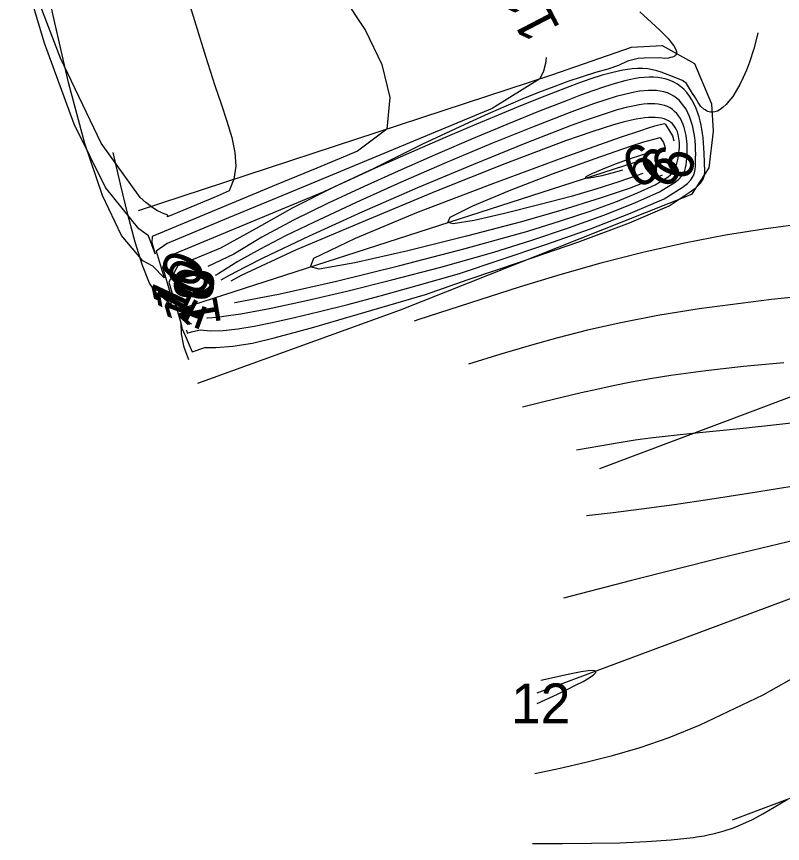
# Model space of a CAD drawing. Extents: x 2602990 to 2605851, y 618069 to 619180.
# Drawn here: x 2603067.49 to 2603105.92, y 618321.38 to 618362.9 of the extents above; entities that cross this region are included whole.
import ezdxf

# ---------------------------------------------------------------- set-up
doc = ezdxf.new("R2010")
doc.units = 0
for name, color, linetype in [('DTM Contours Major', 7, 'Continuous'), ('DTM Contours Major Text', 7, 'Continuous'), ('DTM Contours Minor', 7, 'Continuous'), ('DTM Contours Minor Text', 7, 'Continuous'), ('PH Exist DTM Breakline', 7, 'Continuous')]:
    doc.layers.add(name, color=color, linetype=linetype)

msp = doc.modelspace()

# ---------------------------------------------------------------- linework, layer by layer
at = {"layer": 'DTM Contours Major'}
for points in [[(2603100.888, 618354.321), (2603101.149, 618354.52), (2603101.329, 618354.703), (2603101.443, 618354.877), (2603101.507, 618355.045), (2603101.538, 618355.214), (2603101.551, 618355.387), (2603101.565, 618355.785), (2603101.567, 618355.996), (2603101.563, 618356.211), (2603101.553, 618356.431), (2603101.536, 618356.651), (2603101.517, 618356.829), (2603101.492, 618357.006), (2603101.461, 618357.18), (2603101.424, 618357.352), (2603101.38, 618357.521), (2603101.33, 618357.685), (2603101.259, 618357.879), (2603101.177, 618358.063), (2603101.084, 618358.238), (2603100.98, 618358.402), (2603100.863, 618358.553), (2603100.734, 618358.69), (2603100.605, 618358.802), (2603100.464, 618358.902), (2603100.312, 618358.987), (2603100.148, 618359.059), (2603099.971, 618359.115), (2603099.782, 618359.156), (2603099.598, 618359.18), (2603099.403, 618359.191), (2603099.195, 618359.189), (2603098.975, 618359.173), (2603098.74, 618359.144), (2603098.491, 618359.102), (2603098.057, 618359.007), (2603097.581, 618358.879), (2603097.061, 618358.718), (2603096.495, 618358.527), (2603095.88, 618358.307), (2603095.214, 618358.059), (2603093.371, 618357.343), (2603091.295, 618356.501), (2603089.071, 618355.568), (2603086.786, 618354.577), (2603084.528, 618353.563), (2603082.382, 618352.56), (2603080.99, 618351.88), (2603079.719, 618351.223), (2603078.593, 618350.594), (2603077.634, 618349.992), (2603077.462, 618349.902)], [(2603076.014, 618347.156), (2603076.058, 618347.006), (2603076.27, 618347.068), (2603076.696, 618347.17), (2603077.224, 618347.117), (2603077.863, 618347.138), (2603078.599, 618347.222), (2603079.419, 618347.358), (2603080.31, 618347.534), (2603081.444, 618347.783), (2603082.698, 618348.083), (2603084.112, 618348.444), (2603085.727, 618348.878), (2603087.584, 618349.394), (2603089.722, 618350.003), (2603091.764, 618350.676), (2603094.045, 618351.444), (2603096.283, 618352.245), (2603098.303, 618353.025), (2603099.986, 618353.745), (2603100.888, 618354.321)]]:
    msp.add_lwpolyline(points, dxfattribs=at)
at = {"layer": 'DTM Contours Minor'}
for points in [[(2603075.977, 618364.117), (2603076.486, 618362.486), (2603076.969, 618360.912), (2603077.443, 618359.429), (2603077.757, 618358.507), (2603078.047, 618357.641), (2603078.285, 618356.831), (2603078.441, 618356.076), (2603078.489, 618355.377), (2603078.399, 618354.733), (2603078.151, 618354.143), (2603077.4, 618353.815), (2603075.34, 618352.958), (2603075.058, 618352.844), (2603075.082, 618352.923), (2603074.807, 618353.027), (2603074.531, 618353.166), (2603074.253, 618353.342), (2603073.974, 618353.555), (2603073.693, 618353.808), (2603071.74, 618356.532), (2603069.7, 618360.808), (2603067.588, 618366.326)], [(2603094.07, 618360.84), (2603094.037, 618360.54), (2603093.925, 618360.155), (2603093.74, 618359.764), (2603091.347, 618358.271), (2603081.363, 618354.121), (2603078.13, 618352.784), (2603075.046, 618351.498), (2603074.502, 618351.109), (2603074.891, 618349.777), (2603074.321, 618350.366), (2603073.829, 618350.64), (2603072.761, 618351.899), (2603071.797, 618353.909), (2603070.917, 618356.52), (2603070.099, 618359.581), (2603069.322, 618362.944), (2603068.566, 618366.456)], [(2603083.886, 618363.895), (2603085.002, 618362.191), (2603085.819, 618360.491), (2603086.216, 618358.831), (2603086.07, 618357.248), (2603084.592, 618356.136), (2603082.556, 618355.286), (2603080.523, 618354.446), (2603074.294, 618351.855), (2603074.284, 618351.548), (2603074.448, 618350.989), (2603074.117, 618351.895), (2603073.63, 618352.243), (2603071.944, 618354.314), (2603070.374, 618357.491), (2603068.897, 618361.554), (2603067.489, 618366.281)], [(2603098.764, 618363.128), (2603099.559, 618362.41), (2603099.782, 618362.2), (2603099.982, 618362.002), (2603100.181, 618361.792), (2603100.345, 618361.599), (2603100.472, 618361.425), (2603100.561, 618361.272), (2603100.608, 618361.142), (2603100.611, 618361.036), (2603100.587, 618360.979), (2603100.544, 618360.932), (2603100.483, 618360.894), (2603100.404, 618360.863), (2603100.309, 618360.836), (2603100.198, 618360.814), (2603100.021, 618360.786), (2603099.763, 618360.828), (2603098.975, 618360.8), (2603098.681, 618360.783), (2603098.151, 618360.649), (2603097.702, 618360.43), (2603097.161, 618360.258), (2603096.534, 618360.079), (2603095.865, 618359.869), (2603095.155, 618359.629), (2603094.441, 618359.37), (2603093.687, 618359.08), (2603092.89, 618358.758), (2603092.046, 618358.402), (2603091.151, 618358.011), (2603090.202, 618357.583), (2603087.864, 618356.481), (2603085.376, 618355.246), (2603082.912, 618354.096), (2603075.178, 618350.884), (2603074.82, 618350.323), (2603075.239, 618348.891), (2603075.236, 618348.447), (2603074.768, 618348.839), (2603074.523, 618348.973), (2603074.168, 618349.509), (2603073.809, 618350.397), (2603073.446, 618351.569), (2603073.08, 618352.952), (2603072.713, 618354.476), (2603072.345, 618356.071)], [(2603104.679, 618362.079), (2603104.665, 618361.993), (2603104.487, 618361.276), (2603104.266, 618360.599), (2603104.114, 618360.203), (2603103.951, 618359.83), (2603103.782, 618359.484), (2603103.605, 618359.168), (2603103.424, 618358.886), (2603103.238, 618358.641), (2603103.093, 618358.478), (2603102.947, 618358.342), (2603102.803, 618358.233), (2603102.66, 618358.153), (2603102.522, 618358.104), (2603102.388, 618358.088), (2603102.316, 618358.093), (2603102.246, 618358.109), (2603102.178, 618358.133), (2603102.11, 618358.166), (2603102.043, 618358.206), (2603101.976, 618358.253), (2603101.826, 618358.383), (2603101.7, 618358.581), (2603101.564, 618358.807), (2603101.414, 618359.037), (2603101.261, 618359.29), (2603101.099, 618359.539), (2603100.902, 618359.685), (2603100.269, 618359.942), (2603100.055, 618360.022), (2603099.831, 618360.111), (2603099.618, 618360.174), (2603099.393, 618360.227), (2603099.158, 618360.264), (2603098.911, 618360.282), (2603098.653, 618360.283), (2603098.381, 618360.266), (2603097.917, 618360.202), (2603097.417, 618360.094), (2603096.88, 618359.947), (2603096.304, 618359.763), (2603095.689, 618359.548), (2603095.032, 618359.304), (2603093.99, 618358.9), (2603092.861, 618358.447), (2603091.649, 618357.946), (2603090.36, 618357.404), (2603089, 618356.822), (2603087.573, 618356.204), (2603085.483, 618355.284), (2603083.374, 618354.311), (2603081.349, 618353.298), (2603079.511, 618352.254), (2603077.719, 618351.271), (2603075.575, 618350.381), (2603075.13, 618349.568), (2603075.732, 618347.511), (2603075.757, 618346.97), (2603075.827, 618346.533), (2603075.87, 618346.368), (2603075.916, 618346.216), (2603076.017, 618345.94), (2603076.124, 618345.686)], [(2603101.234, 618354.06), (2603101.583, 618354.303), (2603101.812, 618354.523), (2603101.947, 618354.729), (2603102.01, 618354.925), (2603102.026, 618355.121), (2603101.992, 618356.038), (2603101.96, 618356.555), (2603101.935, 618356.817), (2603101.909, 618357.029), (2603101.876, 618357.239), (2603101.837, 618357.447), (2603101.791, 618357.652), (2603101.738, 618357.853), (2603101.677, 618358.049), (2603101.591, 618358.28), (2603101.492, 618358.501), (2603101.38, 618358.709), (2603101.255, 618358.905), (2603101.117, 618359.085), (2603100.965, 618359.248), (2603100.813, 618359.383), (2603100.649, 618359.502), (2603100.473, 618359.604), (2603100.285, 618359.69), (2603100.085, 618359.758), (2603099.873, 618359.809), (2603099.668, 618359.84), (2603099.453, 618359.856), (2603099.226, 618359.857), (2603098.987, 618359.843), (2603098.736, 618359.814), (2603098.471, 618359.771), (2603098.014, 618359.672), (2603097.519, 618359.537), (2603096.984, 618359.369), (2603096.406, 618359.17), (2603095.784, 618358.943), (2603095.116, 618358.688), (2603093.683, 618358.125), (2603092.099, 618357.482), (2603090.399, 618356.772), (2603088.615, 618356.008), (2603086.781, 618355.204), (2603084.932, 618354.37), (2603083.123, 618353.53), (2603081.39, 618352.679), (2603079.791, 618351.822), (2603078.385, 618350.964), (2603077.094, 618350.348)], [(2603100.541, 618354.582), (2603100.725, 618354.737), (2603100.859, 618354.885), (2603100.953, 618355.027), (2603101.015, 618355.166), (2603101.055, 618355.307), (2603101.082, 618355.452), (2603101.105, 618355.613), (2603101.123, 618355.781), (2603101.136, 618355.954), (2603101.142, 618356.13), (2603101.142, 618356.309), (2603101.136, 618356.488), (2603101.125, 618356.633), (2603101.109, 618356.776), (2603101.088, 618356.918), (2603101.061, 618357.057), (2603101.029, 618357.193), (2603100.991, 618357.326), (2603100.936, 618357.483), (2603100.872, 618357.632), (2603100.797, 618357.773), (2603100.712, 618357.905), (2603100.616, 618358.026), (2603100.509, 618358.136), (2603100.399, 618358.226), (2603100.279, 618358.305), (2603100.148, 618358.372), (2603100.005, 618358.428), (2603099.849, 618358.47), (2603099.68, 618358.5), (2603099.515, 618358.516), (2603099.337, 618358.52), (2603099.147, 618358.513), (2603098.942, 618358.494), (2603098.724, 618358.464), (2603098.49, 618358.421), (2603098.079, 618358.328), (2603097.625, 618358.204), (2603097.125, 618358.051), (2603096.576, 618357.868), (2603095.978, 618357.657), (2603095.327, 618357.418), (2603093.04, 618356.536), (2603090.414, 618355.472), (2603087.615, 618354.295), (2603084.81, 618353.072), (2603082.165, 618351.874), (2603079.847, 618350.768), (2603078.953, 618350.318), (2603078.165, 618349.902), (2603077.746, 618349.665)], [(2603100.194, 618354.843), (2603100.306, 618354.955), (2603100.397, 618355.066), (2603100.469, 618355.176), (2603100.527, 618355.287), (2603100.574, 618355.4), (2603100.613, 618355.516), (2603100.65, 618355.645), (2603100.682, 618355.779), (2603100.708, 618355.915), (2603100.728, 618356.054), (2603100.743, 618356.194), (2603100.751, 618356.334), (2603100.749, 618356.557), (2603100.741, 618356.667), (2603100.728, 618356.775), (2603100.709, 618356.88), (2603100.685, 618356.982), (2603100.648, 618357.102), (2603100.601, 618357.215), (2603100.544, 618357.322), (2603100.476, 618357.421), (2603100.397, 618357.511), (2603100.305, 618357.592), (2603100.21, 618357.657), (2603100.102, 618357.713), (2603099.983, 618357.759), (2603099.849, 618357.794), (2603099.702, 618357.819), (2603099.539, 618357.833), (2603099.378, 618357.835), (2603099.202, 618357.827), (2603099.012, 618357.809), (2603098.806, 618357.781), (2603098.584, 618357.742), (2603098.344, 618357.692), (2603097.921, 618357.589), (2603097.449, 618357.457), (2603096.927, 618357.298), (2603096.352, 618357.11), (2603095.724, 618356.895), (2603095.04, 618356.652), (2603091.986, 618355.508), (2603088.549, 618354.127), (2603084.989, 618352.638), (2603081.488, 618351.164), (2603078.752, 618349.889), (2603078.237, 618349.61)], [(2603082.233, 618350.331), (2603082.405, 618350.767), (2603084.496, 618351.771), (2603087.58, 618353.059), (2603091.299, 618354.487), (2603094.918, 618355.818), (2603097.795, 618356.837), (2603098.81, 618357.181), (2603099.199, 618357.305), (2603099.522, 618357.401), (2603099.786, 618357.471), (2603100.022, 618357.52), (2603100.039, 618357.491), (2603100.051, 618357.475), (2603100.101, 618357.386), (2603100.131, 618357.347), (2603100.213, 618357.215), (2603100.403, 618356.914), (2603100.476, 618356.653)], [(2603089.133, 618352.556), (2603089.241, 618352.823), (2603090.388, 618353.397), (2603092.219, 618354.16), (2603094.382, 618354.993), (2603096.524, 618355.774), (2603098.292, 618356.385), (2603098.96, 618356.6), (2603099.462, 618356.747), (2603099.786, 618356.826), (2603099.947, 618356.569), (2603099.971, 618356.523), (2603099.982, 618356.474), (2603100, 618356.425), (2603100.021, 618356.336), (2603100.024, 618356.324)], [(2603096.034, 618354.781), (2603096.079, 618354.868), (2603096.404, 618355.037), (2603096.923, 618355.258), (2603097.55, 618355.501), (2603098.201, 618355.736), (2603098.923, 618355.975), (2603099.266, 618356.074), (2603099.536, 618356.138), (2603099.546, 618356.097), (2603099.546, 618356.089), (2603099.571, 618356.007), (2603099.572, 618356.002)], [(2603097.911, 618355.178), (2603097.849, 618355.16), (2603097.353, 618355.026), (2603096.853, 618354.903), (2603096.419, 618354.808), (2603096.122, 618354.761), (2603096.034, 618354.781)], [(2603078.422, 618348.534), (2603078.444, 618348.537), (2603080.709, 618348.973), (2603083.546, 618349.613), (2603086.72, 618350.393), (2603089.996, 618351.249), (2603093.14, 618352.115), (2603094.789, 618352.633), (2603096.267, 618353.127), (2603097.559, 618353.596), (2603098.653, 618354.039), (2603099.536, 618354.455), (2603100.194, 618354.843)], [(2603099.891, 618354.94), (2603099.305, 618354.675), (2603098.234, 618354.269), (2603096.77, 618353.774), (2603094.85, 618353.172), (2603092.828, 618352.597), (2603090.075, 618351.866), (2603087.115, 618351.127), (2603084.471, 618350.526), (2603082.669, 618350.211), (2603082.233, 618350.331)], [(2603098.923, 618355.021), (2603098.63, 618354.909), (2603097.719, 618354.597), (2603096.559, 618354.228), (2603095.322, 618353.869), (2603093.697, 618353.435), (2603091.975, 618353.006), (2603090.446, 618352.663), (2603089.402, 618352.486), (2603089.133, 618352.556)], [(2603077.044, 618347.763), (2603077.073, 618347.764), (2603077.558, 618347.807), (2603078.118, 618347.88), (2603078.75, 618347.979), (2603080.262, 618348.258), (2603082.041, 618348.635), (2603084.067, 618349.107), (2603086.321, 618349.67), (2603088.782, 618350.322), (2603091.431, 618351.059), (2603093.299, 618351.656), (2603095.18, 618352.287), (2603096.959, 618352.923), (2603098.522, 618353.537), (2603099.754, 618354.099), (2603100.541, 618354.582)], [(2603075.754, 618347.465), (2603075.781, 618347.255), (2603075.957, 618346.885), (2603076.307, 618346.062), (2603076.938, 618346.276), (2603077.489, 618346.286), (2603078.34, 618346.341), (2603079.321, 618346.506), (2603080.416, 618346.759), (2603081.607, 618347.077), (2603082.408, 618347.303), (2603084.235, 618347.835), (2603088.012, 618348.947), (2603090.156, 618349.688), (2603092.831, 618350.592), (2603095.656, 618351.571), (2603098.251, 618352.534), (2603100.238, 618353.393), (2603101.234, 618354.06)], [(2603107.084, 618352.511), (2603105.086, 618352.24), (2603103.056, 618351.914), (2603101.011, 618351.522), (2603098.907, 618351.047), (2603096.815, 618350.509), (2603094.748, 618349.925), (2603092.718, 618349.311), (2603090.736, 618348.682), (2603087.674, 618347.68), (2603087.446, 618347.605)], [(2603109.288, 618349.099), (2603105.365, 618348.696), (2603101.749, 618348.224), (2603099.674, 618347.882), (2603097.809, 618347.518), (2603096.139, 618347.143), (2603094.648, 618346.768), (2603093.322, 618346.401), (2603091.793, 618345.948), (2603090.16, 618345.443)], [(2603105.985, 618345.516), (2603103.97, 618345.319), (2603102.072, 618345.107), (2603100.324, 618344.872), (2603099.289, 618344.707), (2603098.326, 618344.533), (2603097.431, 618344.355), (2603096.6, 618344.175), (2603095.827, 618343.998), (2603093.952, 618343.546), (2603092.874, 618343.281)], [(2603134.935, 618343.861), (2603134.975, 618343.899), (2603135.204, 618344.44), (2603134.644, 618344.634), (2603133.387, 618344.522), (2603131.584, 618344.18), (2603129.384, 618343.68), (2603126.939, 618343.098), (2603124.397, 618342.507), (2603121.995, 618341.99), (2603119.642, 618341.524), (2603117.338, 618341.101), (2603115.085, 618340.711), (2603112.881, 618340.345), (2603106.295, 618339.281), (2603104.223, 618338.952), (2603102.277, 618338.652), (2603100.48, 618338.386), (2603098.855, 618338.162), (2603097.424, 618337.984), (2603096.088, 618337.829)], [(2603107.147, 618342.56), (2603103.948, 618342.22), (2603101.425, 618341.958), (2603100.785, 618341.89), (2603099.283, 618341.721), (2603098.532, 618341.624), (2603097.72, 618341.501), (2603096.753, 618341.334), (2603095.588, 618341.119)], [(2603114.331, 618337.76), (2603112.957, 618337.752), (2603110.043, 618337.324), (2603106.557, 618336.602), (2603102.795, 618335.707), (2603098.352, 618334.58), (2603094.941, 618333.7)], [(2603093.496, 618324.898), (2603094.77, 618325.165), (2603096.062, 618325.456), (2603097.392, 618325.794), (2603098.777, 618326.204), (2603100.237, 618326.708), (2603101.789, 618327.331), (2603104.959, 618328.852), (2603108.214, 618330.684), (2603111.244, 618332.633), (2603113.738, 618334.504), (2603114.614, 618335.355)], [(2603093.605, 618328.412), (2603094.638, 618328.884), (2603095.123, 618329.114), (2603095.544, 618329.324), (2603095.914, 618329.521), (2603096.217, 618329.698), (2603096.434, 618329.847), (2603096.551, 618329.962), (2603096.549, 618330.036), (2603096.418, 618330.063), (2603096.172, 618330.048), (2603095.829, 618329.998), (2603095.41, 618329.921), (2603094.934, 618329.823), (2603093.795, 618329.57)], [(2603093.387, 618321.383), (2603094.879, 618321.385), (2603096.345, 618321.395), (2603097.761, 618321.421), (2603099.1, 618321.473), (2603100.338, 618321.557), (2603101.449, 618321.683), (2603101.728, 618321.726), (2603101.996, 618321.773), (2603102.257, 618321.825), (2603102.51, 618321.882), (2603102.757, 618321.946), (2603102.999, 618322.016), (2603103.461, 618322.171), (2603103.927, 618322.36), (2603104.413, 618322.59), (2603104.937, 618322.868), (2603105.512, 618323.201), (2603106.157, 618323.598)]]:
    msp.add_lwpolyline(points, dxfattribs=at)
at = {"layer": 'PH Exist DTM Breakline'}
for points in [[(2603183.194, 618372.73), (2603096.745, 618340.197)], [(2603093.621, 618328.945), (2603146.734, 618348.736), (2603185.155, 618362.837)], [(2603073.602, 618353.159), (2603094.35, 618359.964), (2603098.345, 618361.36), (2603099.89, 618361.439), (2603101.515, 618360.53), (2603102.363, 618358.51), (2603102.442, 618357.138), (2603102.219, 618355.294), (2603101.355, 618353.969), (2603086.745, 618348.163), (2603076.562, 618344.481)], [(2603075.808, 618348.259), (2603099.005, 618355.739)], [(2603103.415, 618322.566), (2603163.12, 618345.032), (2603185.717, 618352.612)]]:
    msp.add_lwpolyline(points, dxfattribs=at)

# ---------------------------------------------------------------- texts
at = {"layer": 'DTM Contours Major Text'}
msp.add_text('10', height=2, rotation=62.1923, dxfattribs=at).set_placement((2603075.96, 618347.399))
at = {"layer": 'DTM Contours Minor Text'}
for s, rotation, p in [('11', 117.5158, (2603094.8, 618362.318)), ('9', 206.3791, (2603099.005, 618356.666)), ('9', 229.7896, (2603099.502, 618356.554)), ('9', 251.1628, (2603099.769, 618356.607)), ('10', 65.0693, (2603075.793, 618347.795)), ('10', 69.7383, (2603076.557, 618347.014)), ('10', 99.73, (2603077.761, 618347.443))]:
    msp.add_text(s, height=2, rotation=rotation, dxfattribs=at).set_placement(p)
msp.add_text('12', height=2, dxfattribs=at).set_placement((2603092.305, 618327.412))

doc.saveas('drawing.dxf')
